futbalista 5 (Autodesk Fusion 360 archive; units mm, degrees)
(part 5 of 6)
sketch "Sketch57" plane through (-1.3145, -0.9192, 0) normal (-0.8195, -0.5731, 0) x axis (0.5731, -0.8195, 0)
  line L1 (38.1702, 34.75) -> (84.1847, 34.75)
  line L2 (38.1702, -17.25) -> (38.1702, 34.75)
  line L3 (81.7843, -17.25) -> (38.1702, -17.25)
  line L4 (81.7843, -19.95) -> (81.7843, -17.25)
  line L5 (84.1847, -19.95) -> (81.7843, -19.95)
  line L6 (84.1847, 34.75) -> (84.1847, -19.95)
  line L7 (48.1702, -17.25) -> (38.1702, -17.25)
  line L8 (48.1702, -12.25) -> (48.1702, -17.25)
  line L9 (74.2849, -22.25) -> (74.2849, -17.25)
  line L10 (80.2624, -22.25) -> (74.2849, -22.25)
  line L11 (80.2624, -17.25) -> (80.2624, -22.25)
  line L12 (74.2849, -17.25) -> (80.2624, -17.25)
  line L13 (45.6702, -20) -> (45.6702, -12.25)
  line L14 (50.6702, -20) -> (50.6702, -12.25)
  circle C1 centre (48.1702, -12.25) radius 2.5
  arc A1 centre (77.2736, -17.25) radius 2.9887 clockwise from (74.2849, -17.25) to (80.2624, -17.25)
  point P4 (38.1702, -17.25)
  point P8 (38.1702, -17.25)
  point P10 (48.1702, -12.25)
  point P11 (48.1702, -12.25)
  point P15 (80.2624, -17.25)
  point P17 (80.2624, -17.25)
  point P12 (74.2849, -17.25)
  point P16 (74.2849, -17.25)
  point P19 (45.6702, -12.25)
  point P21 (50.6702, -12.25)
  point P9 (48.1702, -17.25)
  coincident P4 P8
  perpendicular L2 L7
  perpendicular L7 L8
  coincident P10 P11
  tangent L11 A1
  coincident P15 P17
  coincident P12 P16
  coincident C1 P19
  tangent C1 L13
  perpendicular L3 L13
  coincident C1 P21
  tangent C1 L14
  dimension "d457" distance P8 P9 = 10
  dimension "d458" distance P9 P10 = 5
extrude "Extrude91" cut sketch "Sketch57" profile of L3 L7 L8 C1 L12 A1 L13 L14 against normal blind 2
mirror "Mirror1" mirrorStitchTolerance 0.1
sketch "Sketch58" plane through (59.4825, 10.4884, 0) normal (-0.9848, -0.1736, 0) x axis (0.1736, -0.9848, 0)
  line L1 (-54.7182, 34.75) -> (-57.5849, 34.75)
  line L2 (-54.7182, 32.75) -> (-54.7182, 34.75)
  line L3 (-40.9979, 32.75) -> (-54.7182, 32.75)
  line L4 (-40.9979, 39.3) -> (-40.9979, 32.75)
  line L5 (-57.5849, 39.3) -> (-40.9979, 39.3)
  line L6 (-57.5849, 34.75) -> (-57.5849, 39.3)
  line L7 (-54.7182, 39.3) -> (-54.7182, 34.75)
  point P3 (-54.7182, 34.75)
  point P8 (-54.7182, 34.75)
  point P9 (-54.7182, 39.3)
  coincident P3 P8
  coincident L5 P9
  perpendicular L5 L7
extrude "Extrude93" cut sketch "Sketch58" profile of L2 L3 L4 L5 L7 against normal blind 1.5
extrude "Extrude94" cut of existing geometry blind -3
offset_faces "OffsetFaces27" distance -1
sketch "Sketch59" plane through (0, 0, -17.25) normal (0, 0, 1) x axis (-1, 0, 0)
  line L1 (83.7288, 11.3904) -> (80.9129, 9.7647)
  line L2 (32, -74.955) -> (32, -78.2065)
  line L3 (53.851, -57.8417) -> (53.851, -46.8417)
  line L4 (48.851, -57.8417) -> (53.851, -57.8417)
  line L5 (48.851, -46.8417) -> (48.851, -57.8417)
  line L6 (53.851, -46.8417) -> (48.851, -46.8417)
  line L7 (53.851, -6.8417) -> (48.851, -6.8417)
  line L8 (53.851, -17.8417) -> (53.851, -6.8417)
  line L9 (48.851, -17.8417) -> (53.851, -17.8417)
  line L10 (48.851, -6.8417) -> (48.851, -17.8417)
  line L11 (-19.5656, 26.7114) -> (0, 15.4153)
  line L12 (-28.5443, 4.7598) -> (-18.3943, 22.3402)
  line L13 (-57.5696, 17.8226) -> (-32.9156, 3.5886)
  line L14 (-56.1424, 9.7285) -> (-57.5696, 17.8226)
  line L15 (-60.8695, 8.895) -> (-56.1424, 9.7285)
  line L16 (-62.6555, 19.0241) -> (-60.8695, 8.895)
  line L17 (-59.3277, 19.6109) -> (-62.6555, 19.0241)
  line L18 (-59.5626, 19.2042) -> (-59.3277, 19.6109)
  line L19 (-58.9695, 18.8618) -> (-59.5626, 19.2042)
  line L20 (-45.7195, 41.8114) -> (-58.9695, 18.8618)
  line L21 (-23, 28.6943) -> (-45.7195, 41.8114)
  line L22 (-23, 32.2) -> (-23, 28.6943)
  line L23 (-11.5, 32.2) -> (-23, 32.2)
  line L24 (-11.5, 59.2) -> (-11.5, 32.2)
  line L25 (-5.5, 59.2) -> (-11.5, 59.2)
  line L26 (-5.5, 58.2) -> (-5.5, 59.2)
  line L27 (5.5, 58.2) -> (-5.5, 58.2)
  line L28 (5.5, 59.2) -> (5.5, 58.2)
  line L29 (11.5, 59.2) -> (5.5, 59.2)
  line L30 (11.5, 32.2) -> (11.5, 59.2)
  line L31 (23, 32.2) -> (11.5, 32.2)
  line L32 (23, 28.6943) -> (23, 32.2)
  line L33 (45.7195, 41.8114) -> (23, 28.6943)
  line L34 (59.0695, 18.6886) -> (45.7195, 41.8114)
  line L35 (32.9156, 3.5886) -> (59.0695, 18.6886)
  line L36 (18.3943, 22.3402) -> (28.5443, 4.7598)
  line L37 (0, 15.4153) -> (19.5656, 26.7114)
  line L38 (23, -2.1362) -> (13.35, -7.7076)
  line L39 (23, -21.1848) -> (23, -2.1362)
  line L40 (13.35, -21.1848) -> (23, -21.1848)
  line L41 (13.35, -7.7076) -> (13.35, -21.1848)
  line L42 (-13.35, -21.1848) -> (-13.35, -7.7076)
  line L43 (-23, -21.1848) -> (-13.35, -21.1848)
  line L44 (-23, -2.1362) -> (-23, -21.1848)
  line L45 (-13.35, -7.7076) -> (-23, -2.1362)
  line L46 (-80.9129, 9.7647) -> (-83.7288, 11.3904)
  line L47 (-32, -78.2065) -> (-32, -74.955)
  line L48 (-22.0255, 78.4674) -> (-22.0255, 81.579)
  line L49 (-51.7288, 66.816) -> (-48.9129, 65.1903)
  line L50 (34.3708, 72.532) -> (31.3708, 67.3359)
  line L51 (45.6292, 66.032) -> (34.3708, 72.532)
  line L52 (42.6292, 60.8359) -> (45.6292, 66.032)
  line L53 (31.3708, 67.3359) -> (42.6292, 60.8359)
  line L54 (48.9129, 65.1903) -> (51.7288, 66.816)
  line L55 (22.0255, 81.579) -> (22.0255, 78.4674)
  line L56 (-74, 6.5) -> (-80, 6.5)
  line L57 (-74, -6.5) -> (-74, 6.5)
  line L58 (-80, -6.5) -> (-74, -6.5)
  line L59 (-80, 6.5) -> (-80, -6.5)
  line L60 (45.6292, -66.032) -> (42.6292, -60.8359)
  line L61 (34.3708, -72.532) -> (45.6292, -66.032)
  line L62 (31.3708, -67.3359) -> (34.3708, -72.532)
  line L63 (42.6292, -60.8359) -> (31.3708, -67.3359)
  line L64 (74, -6.5) -> (80, -6.5)
  line L65 (74, 6.5) -> (74, -6.5)
  line L66 (80, 6.5) -> (74, 6.5)
  line L67 (80, -6.5) -> (80, 6.5)
  line L68 (-45.6292, -66.032) -> (-34.3708, -72.532)
  line L69 (-42.6292, -60.8359) -> (-45.6292, -66.032)
  line L70 (-31.3708, -67.3359) -> (-42.6292, -60.8359)
  line L71 (-34.3708, -72.532) -> (-31.3708, -67.3359)
  line L72 (-13.35, -60.5) -> (13.35, -60.5)
  line L73 (-13.35, -30.3) -> (-13.35, -60.5)
  line L74 (10.15, -27.1) -> (-10.15, -27.1)
  line L75 (13.35, -60.5) -> (13.35, -30.3)
  line L76 (-34.3708, 72.532) -> (-45.6292, 66.032)
  line L77 (-31.3708, 67.3359) -> (-34.3708, 72.532)
  line L78 (-42.6292, 60.8359) -> (-31.3708, 67.3359)
  line L79 (-45.6292, 66.032) -> (-42.6292, 60.8359)
  line L80 (-52.7675, -48.5711) -> (-54.5535, -38.442)
  line L81 (-54.4417, -48.8663) -> (-52.7675, -48.5711)
  line L82 (-56.2277, -38.7372) -> (-54.4417, -48.8663)
  line L83 (-54.5535, -38.442) -> (-56.2277, -38.7372)
  line L84 (-46.0708, -47.3903) -> (-47.8568, -37.2612)
  line L85 (-50.7979, -48.2238) -> (-46.0708, -47.3903)
  line L86 (-52.5839, -38.0947) -> (-50.7979, -48.2238)
  line L87 (-47.8568, -37.2612) -> (-52.5839, -38.0947)
  line L88 (22.151, -57.8417) -> (22.151, -46.8417)
  line L89 (16.151, -57.8417) -> (22.151, -57.8417)
  line L90 (16.151, -46.8417) -> (16.151, -57.8417)
  line L91 (22.151, -46.8417) -> (16.151, -46.8417)
  line L92 (-64.5876, 18.4639) -> (-41.4358, 58.564)
  line L93 (-62.8391, 8.5477) -> (-64.5876, 18.4639)
  line L94 (-64.5133, 8.2525) -> (-62.8391, 8.5477)
  line L95 (-65.9099, 16.1735) -> (-64.5133, 8.2525)
  line L96 (-71.4358, 6.6024) -> (-65.9099, 16.1735)
  line L97 (-85.2616, 14.5848) -> (-71.4358, 6.6024)
  line L98 (-30, -65.1664) -> (-30, -81.1311)
  line L99 (30, -65.1664) -> (-30, -65.1664)
  line L100 (30, -81.1311) -> (30, -65.1664)
  line L101 (71.4358, 6.6024) -> (85.2616, 14.5848)
  line L102 (41.4358, 58.564) -> (71.4358, 6.6024)
  line L103 (55.2616, 66.5463) -> (41.4358, 58.564)
  line L104 (20.0255, 60.7) -> (20.0255, 82.8712)
  line L105 (-20.0255, 60.7) -> (20.0255, 60.7)
  line L106 (-20.0255, 82.8712) -> (-20.0255, 60.7)
  line L107 (-41.4358, 58.564) -> (-55.2616, 66.5463)
  line L108 (63.1108, 21.0218) -> (59.0695, 18.6886)
  line L109 (49.7608, 44.1446) -> (45.7195, 41.8114)
  line L110 (-63.1108, 21.0218) -> (-59.0695, 18.6886)
  line L111 (-49.7608, 44.1446) -> (-45.7195, 41.8114)
  line L112 (-13.35, -65.1664) -> (-13.35, -60.5)
  line L113 (13.35, -65.1664) -> (13.35, -60.5)
  line L114 (-58.9695, 18.8618) -> (-59.0695, 18.6886)
  arc A1 centre (0, 0) radius 81.5 clockwise from (80.9129, 9.7647) to (32, -74.955)
  arc A2 centre (0, 0) radius 84.5 clockwise from (83.7288, 11.3904) to (32, -78.2065)
  circle C1 centre (-41.0955, 46.0692) radius 1.7
  circle C2 centre (41.0955, 46.0692) radius 1.7
  circle C3 centre (-57.0248, -52.0589) radius 1.7
  arc A3 centre (-21.1656, 23.9402) radius 3.2 clockwise from (-19.5656, 26.7114) to (-18.3943, 22.3402)
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  point P46 (59.0695, 18.6886)
  point P145 (59.0695, 18.6886)
  point P146 (63.1108, 21.0218)
  point P45 (45.7195, 41.8114)
  point P147 (45.7195, 41.8114)
  point P148 (49.7608, 44.1446)
  point P150 (-63.1108, 21.0218)
  point P32 (-45.7195, 41.8114)
  point P151 (-45.7195, 41.8114)
  point P152 (-49.7608, 44.1446)
  point P94 (-13.35, -60.5)
  point P153 (-13.35, -60.5)
  point P154 (-13.35, -65.1664)
  point P93 (13.35, -60.5)
  point P155 (13.35, -60.5)
  point P156 (13.35, -65.1664)
  point P31 (-58.9695, 18.8618)
  point P157 (-58.9695, 18.8618)
  coincident P46 P145
  coincident L102 P146
  perpendicular L102 L108
  coincident P45 P147
  coincident L102 P148
  perpendicular L102 L109
  coincident L92 P150
  perpendicular L92 L110
  coincident P32 P151
  coincident L92 P152
  perpendicular L92 L111
  coincident P94 P153
  coincident L99 P154
  perpendicular L99 L112
  coincident P93 P155
  coincident L99 P156
  perpendicular L99 L113
  coincident P31 P157
  perpendicular L19 L114
extrude "Extrude95" cut sketch "Sketch59" profile of L17 L18 L19 L20 L34 L72 L92 L99 L102 L108 L109 L110 L111 L112 L113 L114 against normal blind 5 and along normal blind 1
extrude "Extrude96" add of existing geometry blind 40
sketch "Sketch60" plane through (0, 61.1848, 0) normal (0, 1, 0) x axis (-1, 0, 0)
  line L1 (-13.35, 0) -> (-13.35, -17.25)
  line L2 (13.35, -17.25) -> (13.35, 0)
  line L3 (23, -17.25) -> (13.35, -17.25)
  line L4 (23, 28.6416) -> (23, -17.25)
  line L5 (-9, 14.6416) -> (9, 14.6416)
  line L6 (-23, -17.25) -> (-23, 28.6416)
  line L7 (-13.35, -17.25) -> (-23, -17.25)
  line L8 (23, 28.6416) -> (-23, 28.6416)
  arc A1 centre (0, 0) radius 13.35 clockwise from (-13.35, 0) to (13.35, 0)
  arc A2 centre (9, 28.6416) radius 14 clockwise from (23, 28.6416) to (9, 14.6416)
  arc A3 centre (-9, 28.6416) radius 14 clockwise from (-9, 14.6416) to (-23, 28.6416)
  point P12 (-23, 28.6416)
  point P15 (-23, 28.6416)
  point P8 (23, 28.6416)
  point P16 (23, 28.6416)
  coincident P12 P15
  coincident P8 P16
fillet "Fillet7" radius 1
extrude "Extrude97" add sketch "Sketch60" along normal blind 3.9816
extrude "Extrude98" cut of existing geometry blind 28.5
sketch "Sketch61" plane through (-23, 0, 0) normal (-1, 0, 0) x axis (0, -1, 0)
  line L1 (-61.1848, 21.1583) -> (13.8152, 21.1583)
  line L2 (-61.1848, 28.6416) -> (-61.1848, 21.1583)
  line L3 (-65.1664, 28.6416) -> (-61.1848, 28.6416)
  line L4 (-65.1664, -17.25) -> (-65.1664, 28.6416)
  line L5 (-2.1362, -17.25) -> (-65.1664, -17.25)
  line L6 (-2.1362, 0) -> (-2.1362, -17.25)
  line L7 (28.6943, -17.25) -> (28.6943, 0)
  line L8 (32.2, -17.25) -> (28.6943, -17.25)
  line L9 (32.2, 4.6416) -> (32.2, -17.25)
  line L10 (22.2, 14.6416) -> (32.2, 4.6416)
  line L11 (13.8152, 14.6416) -> (22.2, 14.6416)
  line L12 (13.8152, 21.1583) -> (13.8152, 14.6416)
  closed curve K1 centre (13.2791, 0)
  circle C1 centre (-12.3417, -11.9) radius 1.7
  circle C2 centre (-52.3417, -11.9) radius 1.7
extrude "Extrude99" cut sketch "Sketch61" profile of C2 against normal blind 9.65
extrude "Extrude100" new body of existing geometry blind 7 second side blind -3
extrude "Extrude101" cut of existing geometry blind -3.2
fillet "Fillet8" radius 3.2
offset_faces "OffsetFaces28" distance 0.4
sketch "Sketch62" plane through (0, 0, -17.25) normal (0, 0, -1) x axis (1, 0, 0)
  line L1 (10.15, -57.3) -> (-10.15, -57.3)
  line L2 (13.35, -30.3) -> (13.35, -54.1)
  line L3 (-10.15, -27.1) -> (10.15, -27.1)
  line L4 (-13.35, -54.1) -> (-13.35, -30.3)
  line L5 (-9.3809, -52) -> (-6.5191, -52)
  line L6 (-6.2839, -51.8642) -> (-4.853, -49.3858)
  line L7 (-4.853, -49.1142) -> (-6.2839, -46.6358)
  line L8 (-6.5191, -46.5) -> (-9.3809, -46.5)
  line L9 (-9.6161, -46.6358) -> (-11.047, -49.1142)
  line L10 (-11.047, -49.3858) -> (-9.6161, -51.8642)
  line L11 (9.6161, -51.8642) -> (11.047, -49.3858)
  line L12 (11.047, -49.1142) -> (9.6161, -46.6358)
  line L13 (4.853, -49.3858) -> (6.2839, -51.8642)
  line L14 (6.2839, -46.6358) -> (4.853, -49.1142)
  line L15 (9.3809, -46.5) -> (6.5191, -46.5)
  line L16 (6.5191, -52) -> (9.3809, -52)
  line L17 (-6.2839, -38.0642) -> (-4.853, -35.5858)
  line L18 (-4.853, -35.3142) -> (-6.2839, -32.8358)
  line L19 (-11.047, -35.5858) -> (-9.6161, -38.0642)
  line L20 (-9.6161, -32.8358) -> (-11.047, -35.3142)
  line L21 (-6.5191, -32.7) -> (-9.3809, -32.7)
  line L22 (-9.3809, -38.2) -> (-6.5191, -38.2)
  line L23 (9.6161, -38.0642) -> (11.047, -35.5858)
  line L24 (11.047, -35.3142) -> (9.6161, -32.8358)
  line L25 (4.853, -35.5858) -> (6.2839, -38.0642)
  line L26 (6.2839, -32.8358) -> (4.853, -35.3142)
  line L27 (9.3809, -32.7) -> (6.5191, -32.7)
  line L28 (6.5191, -38.2) -> (9.3809, -38.2)
  arc A1 centre (-10.15, -54.1) radius 3.2 clockwise from (-10.15, -57.3) to (-13.35, -54.1)
  arc A2 centre (10.15, -54.1) radius 3.2 clockwise from (13.35, -54.1) to (10.15, -57.3)
  arc A3 centre (10.15, -30.3) radius 3.2 clockwise from (10.15, -27.1) to (13.35, -30.3)
  arc A4 centre (-10.15, -30.3) radius 3.2 clockwise from (-13.35, -30.3) to (-10.15, -27.1)
  circle C1 centre (-7.95, -49.25) radius 1.5
  circle C2 centre (7.95, -49.25) radius 1.5
  circle C3 centre (-7.95, -35.45) radius 1.5
  circle C4 centre (7.95, -35.45) radius 1.5
  circle C5 centre (-7.95, -49.25) radius 3.1
  circle C6 centre (7.95, -49.25) radius 1.5
  circle C7 centre (7.95, -49.25) radius 3.1
  circle C8 centre (-7.95, -35.45) radius 1.5
  circle C9 centre (-7.95, -35.45) radius 3.1
  circle C10 centre (7.95, -35.45) radius 1.5
  circle C11 centre (7.95, -35.45) radius 3.1
  point P19 (-6.5191, -52)
  point P20 (-9.3809, -52)
  concentric C1 C5
  coincident C5 P19
  coincident C5 P20
  dimension "d496" diameter C5 = 6.2
  dimension "d499" C-Pattern1-Angle = 360
  dimension "d502" R-Pattern1-uDistance = 15.9
  dimension "d503" R-Pattern1-vDistance = 13.8
extrude "Extrude102" new body sketch "Sketch62" profile of A1 L1 A2 L2 A3 L3 A4 L4 C5 L5 L6 L7 L8 L9 L10 L11 L12 L13 L14 L15 C7 L16 L17 L18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 against normal blind 4
offset_faces "OffsetFaces29" distance -0.2
offset_faces "OffsetFaces30" distance 0.2
extrude "Extrude105" new body sketch "Sketch62" profile of C1 C5 L5 L6 L7 L8 L9 L10 against normal blind 3
move "Move5"
move "Move6"
copy_paste_bodies "CopyPasteBodies1"
move "Move7"
move "Move8"
combine "Combine6"
sketch "Sketch63" plane through (23, 0, 0) normal (1, 0, 0) x axis (0, 1, 0)
  line L1 (-13.8152, 21.1583) -> (61.1848, 21.1583)
  line L2 (-13.8152, 14.6416) -> (-13.8152, 21.1583)
  line L3 (-22.2, 14.6416) -> (-13.8152, 14.6416)
  line L4 (-32.2, 4.6416) -> (-22.2, 14.6416)
  line L5 (-32.2, -17.25) -> (-32.2, 4.6416)
  line L6 (-28.6943, -17.25) -> (-32.2, -17.25)
  line L7 (-28.6943, 0) -> (-28.6943, -17.25)
  line L8 (2.1362, -17.25) -> (2.1362, 0)
  line L9 (65.1664, -17.25) -> (2.1362, -17.25)
  line L10 (65.1664, 28.6416) -> (65.1664, -17.25)
  line L11 (61.1848, 28.6416) -> (65.1664, 28.6416)
  line L12 (61.1848, 21.1583) -> (61.1848, 28.6416)
  line L13 (7.7076, 0) -> (7.7076, -17.25)
  line L14 (-15.4153, 0) -> (-15.4153, -2.75)
  line L15 (-15.4153, -12.75) -> (-15.4153, -17.25)
  line L16 (61.1848, 14.6416) -> (-13.8152, 14.6416)
  line L17 (-13.8152, 14.6416) -> (61.1848, 14.6416)
  line L18 (33.6848, 10.6416) -> (33.6848, 12.6416)
  line L19 (13.6848, 10.6416) -> (33.6848, 10.6416)
  line L20 (13.6848, 12.6416) -> (13.6848, 10.6416)
  line L21 (33.6848, 12.6416) -> (13.6848, 12.6416)
  line L22 (17.7076, -17.25) -> (7.7076, -17.25)
  line L23 (17.7076, -17.25) -> (17.7076, 8.6416)
  line L24 (17.7076, 8.6416) -> (55.1664, 8.6416)
  line L25 (55.1664, -17.25) -> (55.1664, 8.6416)
  line L26 (17.7076, -17.25) -> (21.7076, -13.25)
  line L27 (51.1666, -13.25) -> (21.7076, -13.25)
  line L28 (55.1664, -17.25) -> (51.1666, -13.25)
  line L29 (51.1664, -17.25) -> (47.1666, -13.25)
  line L30 (21.7076, -17.25) -> (25.7076, -13.25)
  line L31 (-32.2, -2.75) -> (-29.7, -17.25)
  closed curve K1 centre (-13.2791, 0)
  closed curve K2 centre (0, 0)
  closed curve K3 centre (0, 0)
  closed curve K4 centre (-15.4153, -7.75)
  point P16 (7.7076, -17.25)
  point P33 (7.7076, -17.25)
  point P37 (55.1664, -17.25)
  point P44 (-29.7, -17.25)
  point P45 (-32.2, -2.75)
  point P29 (33.6848, 12.6416)
  point P30 (33.6848, 10.6416)
  point P31 (13.6848, 10.6416)
  point P34 (17.7076, -17.25)
  point P38 (21.7076, -13.25)
  point P39 (51.1666, -13.25)
  perpendicular L17 L18
  coincident P16 P33
  perpendicular L13 L22
  perpendicular L22 L23
  coincident L9 P37
  perpendicular L9 L25
  perpendicular L25 L27
  coincident L6 P44
  coincident L5 P45
  dimension "d509" distance P29 P30 = 2
  dimension "d510" distance P30 P31 = 20
  dimension "d511" distance P33 P34 = 10
  dimension "d563" distance P38 P39 = 29.459 (= "33.459 mm - 4 mm")
extrude "Extrude103" cut sketch "Sketch63" profile of L9 L23 L24 L25 against normal blind 23
extrude "Extrude104" cut sketch "Sketch63" profile of L18 L19 L20 L21 against normal blind 46
offset_faces "OffsetFaces31" distance -0.6
extrude "Extrude106" add of existing geometry blind -8.851 (= "-30.851 mm + 22 mm") second side blind 12.851
extrude "Extrude107" cut of existing geometry blind -8.851
sketch "Sketch64" plane through (-23, 0, 0) normal (-1, 0, 0) x axis (0, -1, 0)
  line L1 (-33.6848, 10.6416) -> (-13.6848, 10.6416)
  line L2 (-33.6848, 12.6416) -> (-33.6848, 10.6416)
  line L3 (-13.6848, 12.6416) -> (-33.6848, 12.6416)
  line L4 (-13.6848, 10.6416) -> (-13.6848, 12.6416)
  line L5 (-61.1848, 21.1583) -> (13.8152, 21.1583)
  line L6 (-61.1848, 28.6416) -> (-61.1848, 21.1583)
  line L7 (-65.1664, 28.6416) -> (-61.1848, 28.6416)
  line L8 (-65.1664, -17.25) -> (-65.1664, 28.6416)
  line L9 (-2.829, -17.25) -> (-65.1664, -17.25)
  line L10 (-2.829, 0) -> (-2.829, -17.25)
  line L11 (29.3871, -17.25) -> (29.3871, 0)
  line L12 (32.2, -17.25) -> (29.3871, -17.25)
  line L13 (32.2, 4.6416) -> (32.2, -17.25)
  line L14 (22.2, 14.6416) -> (32.2, 4.6416)
  line L15 (13.8152, 14.6416) -> (22.2, 14.6416)
  line L16 (13.8152, 21.1583) -> (13.8152, 14.6416)
  circle C1 centre (-52.3417, -11.9) radius 1.7
  closed curve K1 centre (13.2791, 0)
  circle C2 centre (-12.3417, -11.9) radius 1.7
  circle C3 centre (-52.3417, -11.9) radius 3
  circle C4 centre (-12.3417, -11.9) radius 3
  concentric C1 C3
  concentric C2 C4
  dimension "d528" diameter C3 = 6
  dimension "d529" diameter C4 = 6
extrude "Extrude108" new body sketch "Sketch64" profile of C1 C2 C3 C4 along normal blind 15 and along normal blind 4
copy_paste_bodies "CopyPasteBodies2"
move "Move9"
extrude "Extrude109" add of existing geometry blind 7 second side blind -3
sketch "Sketch65" plane through (-9.9995, 56.71, 0) normal (0.1736, -0.9848, 0) x axis (0.9848, 0.1736, 0)
  line L1 (58.0967, 22.35) -> (58.9501, 22.35)
  line L2 (58.0967, 19.45) -> (58.0967, 22.35)
  line L3 (58.7501, 19.45) -> (58.0967, 19.45)
  line L4 (58.7501, 4.55) -> (58.7501, 19.45)
  line L5 (58.0967, 4.55) -> (58.7501, 4.55)
  line L6 (58.0967, 1.4) -> (58.0967, 4.55)
  line L7 (58.7501, 1.4) -> (58.0967, 1.4)
  line L8 (58.7501, -14.9) -> (58.7501, 1.4)
  line L9 (58.0967, -14.9) -> (58.7501, -14.9)
  line L10 (58.0967, -19.95) -> (58.0967, -14.9)
  line L11 (60.4001, -19.95) -> (58.0967, -19.95)
  line L12 (60.4001, 34.75) -> (60.4001, -19.95)
  line L13 (58.9501, 34.75) -> (60.4001, 34.75)
  line L14 (58.9501, 22.35) -> (58.9501, 34.75)
  line L15 (58.0967, 19.45) -> (43.2001, 19.45)
  line L16 (43.2001, 19.45) -> (43.2001, 5.8429)
  line L17 (43.2001, 5.8429) -> (44.493, 4.55)
  line L18 (44.493, 4.55) -> (58.0967, 4.55)
  line L19 (43.2001, 22.35) -> (58.0967, 22.35)
  line L20 (58.0967, 1.4) -> (44.9001, 1.4)
  line L21 (44.9001, 1.4) -> (44.9001, -14.9)
  line L22 (44.9001, -14.9) -> (58.0967, -14.9)
  line L23 (43.2001, 34.75) -> (43.2001, 22.35)
  line L24 (43.2167, -16.95) -> (43.2167, 0)
  curve K1 (43.2167, 0) -> (-16.8565, 0)
  line L25 (58.0967, -16.95) -> (43.2167, -16.95)
  line L26 (34.178, 22.35) -> (43.2001, 22.35)
  point P29 (43.2167, -16.95)
  point P31 (43.2167, -16.95)
  point P32 (58.0967, -16.95)
  point P22 (43.2001, 22.35)
  point P33 (43.2001, 22.35)
  point P34 (34.178, 22.35)
  coincident P29 P31
  coincident L10 P32
  perpendicular L10 L25
  coincident P22 P33
  coincident K1 P34
  perpendicular L23 L26
extrude "Extrude110" add sketch "Sketch65" profile of L2 L6 L10 L15 L16 L17 L18 L19 L20 L21 L22 L24 K1 L25 L26 against normal blind 29
sketch "Sketch66" plane through (0, 0, 22.35) normal (0, 0, 1) x axis (-1, 0, 0)
  line L1 (-30.4818, -75.9085) -> (-29.9937, -78.6767)
  line L2 (-20.754, -81.6022) -> (-20.754, -79.1234)
  line L3 (-42.1787, -95.3578) -> (-46.6309, -70.1085)
  line L4 (-18.6235, -91.2044) -> (-42.1787, -95.3578)
  line L5 (-23.6593, -62.645) -> (-18.6235, -91.2044)
  line L6 (-48.055, -66.9466) -> (-23.6593, -62.645)
  line L7 (-47.6146, -69.4441) -> (-48.055, -66.9466)
  line L8 (-25.681, -65.5766) -> (-47.6146, -69.4441)
  line L9 (-25.681, -65.5766) -> (-22.9598, -81.0092)
  line L10 (-32.1039, -66.7092) -> (-30.4818, -75.9085)
  line L11 (-30.0823, -63.7775) -> (-27.2822, -79.6575)
  arc A1 centre (0, 0) radius 81.8 clockwise from (-20.754, -79.1234) to (-30.4818, -75.9085)
  arc A2 centre (0, 0) radius 84.2 clockwise from (-20.754, -81.6022) to (-29.9937, -78.6767)
  arc A3 centre (0, 0) radius 84.2 clockwise from (-46.6309, -70.1085) to (-47.6146, -69.4441)
  circle C1 centre (0, 0) radius 84.2
  circle C2 centre (0, 0) radius 81.8
  point P1 (0, 0)
  point P13 (0, 0)
  point P7 (-46.6309, -70.1085)
  point P12 (-47.6146, -69.4441)
  point P14 (-47.6146, -69.4441)
  point P16 (-22.9598, -81.0092)
  point P18 (-32.1039, -66.7092)
  point P19 (-30.0823, -63.7775)
  point P20 (-27.2822, -79.6575)
  point P17 (-30.4818, -75.9085)
  point P15 (-25.681, -65.5766)
  coincident P1 P13
  coincident P7 C1
  coincident P12 P14
  perpendicular L5 L8
  coincident C1 P16
  coincident L8 P18
  perpendicular L8 L10
  coincident L6 P19
  coincident C1 P20
  concentric C1 C2
  coincident P17 C2
  dimension "d540" distance P14 P15 = 22.272
extrude "Extrude111" cut sketch "Sketch66" profile of L1 A1 A2 L3 L4 L5 L6 A3 C1 L8 L9 L10 L11 C2 along normal blind 12.4 and against normal blind 37.25
sketch "Sketch67" plane through (0, 0, 41.4) normal (0, 0, 1) x axis (-1, 0, 0)
  line L1 (14, 32.2) -> (20.5595, 32.2)
  line L2 (14, 17.8152) -> (14, 32.2)
  line L3 (-14, 17.8152) -> (14, 17.8152)
  line L4 (-14, 32.2) -> (-14, 17.8152)
  line L5 (-20.5595, 32.2) -> (-14, 32.2)
  line L6 (-48.2472, 71.7946) -> (-20.5595, 32.2)
  line L7 (20.5595, 32.2) -> (48.2472, 71.7946)
  line L8 (-59.5395, 10.912) -> (-60.091, 10.8147)
  line L9 (-56.7009, 3.4516) -> (-57.8018, 9.6952)
  line L10 (-58.4691, 1.6166) -> (-57.9176, 1.7139)
  line L11 (-61.3077, 9.0771) -> (-60.2068, 2.8334)
  line L12 (-58.5616, -6.4972) -> (-57.813, -10.7427)
  line L13 (-57.8862, -5.2447) -> (-58.4438, -5.9974)
  line L14 (-56.1766, -4.7622) -> (-57.4768, -4.9914)
  line L15 (-54.4512, -10.8044) -> (-55.4236, -5.2894)
  line L16 (-56.2786, -11.7866) -> (-54.9784, -11.5574)
  line L17 (-57.5313, -11.172) -> (-56.75, -11.6887)
  line L18 (-56.2173, -19.7921) -> (-55.4687, -24.0376)
  line L19 (-55.542, -18.5396) -> (-56.0995, -19.2923)
  line L20 (-53.8324, -18.0571) -> (-55.1325, -18.2863)
  line L21 (-52.1069, -24.0993) -> (-53.0794, -18.5843)
  line L22 (-53.9343, -25.0815) -> (-52.6342, -24.8523)
  line L23 (-55.1871, -24.4669) -> (-54.4057, -24.9836)
  line L24 (-23, 13.8152) -> (-23, -61.1848)
  line L25 (23, 13.8152) -> (-23, 13.8152)
  line L26 (23, -61.1848) -> (23, 13.8152)
  line L27 (-23, -61.1848) -> (23, -61.1848)
  line L28 (-47.0259, -36.2146) -> (-47.4127, -34.0213)
  line L29 (-69, 10) -> (-69, -10)
  line L30 (-67, -10) -> (-67, 10)
  line L31 (-71, -10) -> (-69, -10)
  line L32 (-71, 10) -> (-71, -10)
  line L33 (-69, 10) -> (-71, 10)
  line L34 (-65, 10) -> (-67, 10)
  line L35 (-65, -10) -> (-65, 10)
  line L36 (-67, -10) -> (-65, -10)
  line L37 (0, -22.5) -> (0, -1.75)
  line L38 (71, 10) -> (71, -10)
  line L39 (69, 10) -> (69, -10)
  line L40 (71, -10) -> (69, -10)
  line L41 (67, -10) -> (65, -10)
  line L42 (65, -10) -> (65, 10)
  line L43 (67, -10) -> (67, 10)
  line L44 (69, 10) -> (71, 10)
  line L45 (65, 10) -> (67, 10)
  circle C1 centre (41.0955, 46.0692) radius 3
  circle C2 centre (-57.0248, -52.0589) radius 3
  circle C3 centre (-41.0955, 46.0692) radius 3
  circle C4 centre (76.0955, -10.3372) radius 3
  circle C5 centre (47, -60.7321) radius 3
  circle C6 centre (-76.0955, -10.3372) radius 3
  arc A1 centre (0, 0) radius 86.5 clockwise from (48.2472, 71.7946) to (-48.2472, 71.7946)
  arc A2 centre (-59.8305, 9.3375) radius 1.5 clockwise from (-61.3077, 9.0771) to (-60.091, 10.8147)
  arc A3 centre (-59.279, 9.4348) radius 1.5 clockwise from (-59.5395, 10.912) to (-57.8018, 9.6952)
  arc A4 centre (-58.1781, 3.1911) radius 1.5 clockwise from (-56.7009, 3.4516) to (-57.9176, 1.7139)
  arc A5 centre (-58.7296, 3.0938) radius 1.5 clockwise from (-58.4691, 1.6166) to (-60.2068, 2.8334)
  arc A6 centre (-57.1728, -10.6298) radius 0.65 clockwise from (-57.5313, -11.172) to (-57.813, -10.7427)
  arc A7 centre (-57.9214, -6.3843) radius 0.65 clockwise from (-58.5616, -6.4972) to (-58.4438, -5.9974)
  arc A8 centre (-57.3639, -5.6316) radius 0.65 clockwise from (-57.8862, -5.2447) to (-57.4768, -4.9914)
  arc A9 centre (-56.0637, -5.4023) radius 0.65 clockwise from (-56.1766, -4.7622) to (-55.4236, -5.2894)
  arc A10 centre (-55.0913, -10.9172) radius 0.65 clockwise from (-54.4512, -10.8044) to (-54.9784, -11.5574)
  arc A11 centre (-56.3915, -11.1465) radius 0.65 clockwise from (-56.2786, -11.7866) to (-56.75, -11.6887)
  arc A12 centre (-55.5772, -19.6792) radius 0.65 clockwise from (-56.2173, -19.7921) to (-56.0995, -19.2923)
  arc A13 centre (-55.0196, -18.9265) radius 0.65 clockwise from (-55.542, -18.5396) to (-55.1325, -18.2863)
  arc A14 centre (-53.7195, -18.6972) radius 0.65 clockwise from (-53.8324, -18.0571) to (-53.0794, -18.5843)
  arc A15 centre (-52.7471, -24.2121) radius 0.65 clockwise from (-52.1069, -24.0993) to (-52.6342, -24.8523)
  arc A16 centre (-54.0472, -24.4414) radius 0.65 clockwise from (-53.9343, -25.0815) to (-54.4057, -24.9836)
  arc A17 centre (-54.8286, -23.9247) radius 0.65 clockwise from (-55.1871, -24.4669) to (-55.4687, -24.0376)
  arc A18 centre (-50.1737, -35.6389) radius 3.2 clockwise from (-47.0259, -36.2146) to (-47.4127, -34.0213)
  point P72 (-67, -10)
  point P88 (67, -10)
  point P73 (-69, -10)
  point P85 (69, -10)
  point P74 (-69, 10)
  point P86 (69, 10)
  point P75 (-67, 10)
  point P90 (67, 10)
  point P77 (-71, -10)
  point P83 (71, -10)
  point P78 (-71, 10)
  point P84 (71, 10)
  point P79 (-65, 10)
  point P89 (65, 10)
  point P80 (-65, -10)
  point P87 (65, -10)
  parallel L29 L30
  perpendicular L29 L31
  perpendicular L31 L32
  perpendicular L29 L33
  perpendicular L30 L34
  perpendicular L34 L35
  perpendicular L30 L36
  symmetric P72 L37 P88
  symmetric P73 L37 P85
  symmetric P74 L37 P86
  symmetric P75 L37 P90
  symmetric P77 L37 P83
  symmetric P78 L37 P84
  symmetric P79 L37 P89
  symmetric P80 L37 P87
extrude "Extrude112" cut sketch "Sketch67" profile of L29 L30 L31 L32 L33 L34 L35 L36 L38 L39 L40 L41 L42 L43 L44 L45 against normal blind 8.65
extrude "Extrude113" new body sketch "Sketch12" profile of C1 L1 L2 L3 L7 L11 along normal blind 100
offset_faces "OffsetFaces32" distance 0.5
combine "Combine7"
extrude "Extrude114" cut sketch "Sketch66" profile of A2 L3 L4 L5 C1 against normal blind 39.3
combine "Combine8"
sketch "Sketch68" plane through (42.5438, 7.5016, 0) normal (0.9848, 0.1736, 0) x axis (-0.1736, 0.9848, 0)
  line L1 (60.1209, 5.7183) -> (60.3849, 5.7183)
  line L2 (60.1209, 1.0474) -> (60.1209, 5.7183)
  line L3 (60.1209, 1.0474) -> (69.4611, 1.0474)
  line L4 (72.273, 34.75) -> (72.273, 5.5341)
  line L5 (69.4621, 34.75) -> (72.273, 34.75)
  line L6 (69.4621, 22.35) -> (69.4621, 34.75)
  line L7 (60.1209, 22.35) -> (69.4621, 22.35)
  line L8 (60.1209, 19.45) -> (60.1209, 22.35)
  line L9 (57.5849, 19.45) -> (60.1209, 19.45)
  line L10 (57.5849, 18.2817) -> (57.5849, 19.45)
  line L11 (60.3849, 18.2817) -> (57.5849, 18.2817)
  line L12 (60.3849, 17.55) -> (60.3849, 18.2817)
  line L13 (60.8321, 17.55) -> (60.3849, 17.55)
  line L14 (60.8321, 6.45) -> (60.8321, 17.55)
  line L15 (60.3849, 6.45) -> (60.8321, 6.45)
  line L16 (60.3849, 5.7183) -> (60.3849, 6.45)
  line L17 (60.8321, 18.2817) -> (60.3849, 18.2817)
  line L18 (60.8321, 17.55) -> (60.8321, 18.2817)
  line L19 (60.8321, 5.7183) -> (60.3849, 5.7183)
  line L20 (60.8321, 6.45) -> (60.8321, 5.7183)
  line L21 (57.5849, 5.4619) -> (60.1209, 5.4619)
  line L22 (60.8321, 5.4619) -> (60.8321, 5.7183)
  line L23 (60.1209, 5.4619) -> (60.8321, 5.4619)
  line L24 (57.5849, 18.2817) -> (57.5849, 5.4619)
  line L25 (60.6849, 7.3185) -> (60.9849, 7.3185)
  line L26 (60.9849, 17.25) -> (60.9849, 7.3185)
  line L27 (60.6849, 17.25) -> (60.9849, 17.25)
  line L28 (60.6849, 7.3185) -> (60.6849, 17.25)
  line L29 (60.9849, 18.2817) -> (60.8321, 18.2817)
  line L30 (60.9849, 17.25) -> (60.9849, 18.2817)
  line L31 (60.9849, 5.4619) -> (60.8321, 5.4619)
  line L32 (60.9849, 7.3185) -> (60.9849, 5.4619)
  closed curve K1 centre (245, 0)
  point P15 (60.3849, 18.2817)
  point P20 (60.3849, 18.2817)
  point P17 (60.8321, 17.55)
  point P22 (60.8321, 17.55)
  point P2 (60.3849, 5.7183)
  point P23 (60.3849, 5.7183)
  point P18 (60.8321, 6.45)
  point P25 (60.8321, 6.45)
  point P26 (60.1209, 5.4619)
  point P29 (60.1209, 5.4619)
  point P27 (57.5849, 5.4619)
  point P30 (57.5849, 5.4619)
  point P14 (57.5849, 18.2817)
  point P31 (57.5849, 18.2817)
  point P34 (60.9849, 17.25)
  point P37 (60.9849, 17.25)
  point P32 (60.9849, 7.3185)
  point P39 (60.9849, 7.3185)
  coincident P15 P20
  perpendicular L14 L17
  coincident P17 P22
  perpendicular L13 L18
  coincident P2 P23
  perpendicular L16 L19
  coincident P18 P25
  perpendicular L15 L20
  perpendicular L21 L22
  coincident P26 P29
  perpendicular L2 L23
  coincident P27 P30
  coincident P14 P31
  perpendicular L26 L29
  coincident P34 P37
  perpendicular L27 L30
  perpendicular L22 L31
  coincident P32 P39
  perpendicular L31 L32
extrude "Extrude115" cut sketch "Sketch68" profile of L1 L2 L11 L12 L13 L14 L15 L16 L17 L18 L19 L20 L21 L22 L23 L24 L25 L26 L27 L28 L29 L30 L31 L32 along normal blind 2 and against normal blind 0.8
extrude "Extrude116" cut of existing geometry blind 16.35
sketch "Sketch69" plane through (41.756, 7.3627, 0) normal (0.9848, 0.1736, 0) x axis (-0.1736, 0.9848, 0)
  line L1 (60.1209, 7.3185) -> (60.6849, 7.3185)
  line L2 (60.6849, 7.3185) -> (60.9849, 7.3185)
  line L3 (60.9849, 18.2817) -> (60.9849, 7.3185)
  line L4 (60.1209, 18.2817) -> (60.9849, 18.2817)
  line L5 (60.1209, 19.45) -> (60.1209, 18.2817)
  line L6 (57.5849, 19.45) -> (60.1209, 19.45)
  line L7 (57.5849, 7.3185) -> (57.5849, 19.45)
  line L8 (57.5849, 7.3185) -> (60.1209, 7.3185)
  line L9 (60.9849, 19.45) -> (60.9849, 18.2817)
  line L10 (60.1209, 19.45) -> (60.9849, 19.45)
  line L11 (60.1209, 4.55) -> (57.5849, 4.55)
  line L12 (60.1209, 4.55) -> (57.5849, 4.55)
  line L13 (57.5849, 4.55) -> (57.5849, 7.3185)
  line L14 (60.9849, 4.55) -> (60.1209, 4.55)
  line L15 (60.9849, 7.3185) -> (60.9849, 4.55)
  point P5 (60.9849, 18.2817)
  point P10 (60.9849, 18.2817)
  point P7 (60.1209, 19.45)
  point P12 (60.1209, 19.45)
  point P9 (57.5849, 7.3185)
  point P15 (57.5849, 7.3185)
  point P14 (57.5849, 4.55)
  point P16 (57.5849, 4.55)
  point P13 (60.1209, 4.55)
  point P17 (60.1209, 4.55)
  point P4 (60.9849, 7.3185)
  point P19 (60.9849, 7.3185)
  coincident P5 P10
  perpendicular L6 L9
  coincident P7 P12
  perpendicular L5 L10
  coincident P9 P15
  coincident P14 P16
  coincident P13 P17
  perpendicular L3 L14
  coincident P4 P19
  perpendicular L2 L15
extrude "Extrude117" cut sketch "Sketch69" along normal blind 0.8
extrude "Extrude118" cut sketch "Sketch63" profile of L5 L6 L9 L26 L27 L29 L30 against normal blind 46
extrude "Extrude119" cut of existing geometry blind -5
extrude "Extrude120" cut of existing geometry blind -5
extrude "Extrude121" cut of existing geometry blind -5
extrude "Extrude122" cut of existing geometry blind -5
chamfer "Chamfer9" distance 10
sketch "Sketch71" plane through (23, 0, 0) normal (1, 0, 0) x axis (0, 1, 0)
  line L1 (-29.7, -17.25) -> (-32.2, -2.75)
  line L2 (-29.3871, -17.25) -> (-29.7, -17.25)
  line L3 (-29.3871, 0) -> (-29.3871, -17.25)
  line L4 (2.829, -17.25) -> (2.829, 0)
  line L5 (17.7076, -17.25) -> (2.829, -17.25)
  line L6 (17.7076, 8.6416) -> (17.7076, -17.25)
  line L7 (45.1664, 8.6416) -> (17.7076, 8.6416)
  line L8 (55.1664, -1.3584) -> (45.1664, 8.6416)
  line L9 (55.1664, -17.25) -> (55.1664, -1.3584)
  line L10 (65.1664, -17.25) -> (55.1664, -17.25)
  line L11 (65.1664, 28.6416) -> (65.1664, -17.25)
  line L12 (61.1848, 28.6416) -> (65.1664, 28.6416)
  line L13 (61.1848, 21.1583) -> (61.1848, 28.6416)
  line L14 (-13.8152, 21.1583) -> (61.1848, 21.1583)
  line L15 (-13.8152, 14.6416) -> (-13.8152, 21.1583)
  line L16 (-22.2, 14.6416) -> (-13.8152, 14.6416)
  line L17 (-32.2, 4.6416) -> (-22.2, 14.6416)
  line L18 (-32.2, -2.75) -> (-32.2, 4.6416)
  line L19 (38.6848, 12.6416) -> (33.6848, 12.6416)
  line L20 (38.6848, 10.6416) -> (38.6848, 12.6416)
  line L21 (33.6848, 10.6416) -> (38.6848, 10.6416)
  line L22 (8.6848, 10.6416) -> (33.6848, 10.6416)
  line L23 (8.6848, 12.6416) -> (8.6848, 10.6416)
  line L24 (33.6848, 12.6416) -> (8.6848, 12.6416)
  line L25 (61.2228, 5.3131) -> (56.5304, 0.6208)
  line L26 (61.2228, 14.6979) -> (56.5304, 19.3903)
  line L27 (56.5304, 19.3903) -> (51.838, 14.6979)
  line L28 (51.838, 5.3131) -> (56.5304, 0.6208)
  line L29 (58.8766, 17.0441) -> (54.1842, 17.0441)
  line L30 (58.8766, 2.9669) -> (58.8766, 17.0441)
  line L31 (54.1842, 2.9669) -> (58.8766, 2.9669)
  line L32 (54.1842, 17.0441) -> (54.1842, 2.9669)
  line L33 (47.1456, 10.0055) -> (51.838, 14.6979)
  line L34 (51.838, 5.3131) -> (47.1456, 10.0055)
  line L35 (51.838, 5.3131) -> (61.2228, 14.6979)
  line L36 (2.829, -17.25) -> (-29.3871, -17.25)
  line L37 (-22.0468, -17.25) -> (-32.2, -2.75)
  closed curve K1 centre (-13.2791, 0)
  arc A1 centre (56.5304, 10.0055) radius 6.636 clockwise from (61.2228, 14.6979) to (61.2228, 5.3131)
  arc A2 centre (56.5304, 10.0055) radius 6.636 clockwise from (51.838, 5.3131) to (51.838, 14.6979)
  point P38 (58.8766, 2.9669)
  point P36 (54.1842, 17.0441)
  point P4 (-29.3871, -17.25)
  point P41 (-29.3871, -17.25)
  point P8 (2.829, -17.25)
  point P42 (2.829, -17.25)
  point P2 (-32.2, -2.75)
  point P43 (-32.2, -2.75)
  point P44 (-22.0468, -17.25)
  tangent L25 A1
  tangent L26 A1
  tangent A2 L27
  tangent A2 L28
  horizontal L29
  vertical L30
  horizontal L31
  vertical L32
  midpoint L25 P38
  midpoint L27 P36
  tangent A2 L33
  perpendicular L28 L33
  tangent A2 L34
  perpendicular L28 L35
  coincident P4 P41
  coincident P8 P42
  coincident P2 P43
  coincident L36 P44
extrude "Extrude123" cut sketch "Sketch71" profile of L1 L2 L3 L25 L26 A1 A2 L27 L28 L29 L30 L31 L32 L33 L34 L35 L36 L37 against normal blind 46
work_plane "WorkPlane3" RotateAngle 0
sketch "Sketch72" plane through (-2.0687, 0, 2.7395) normal (-0.6026, 0, 0.798) x axis (-0.798, 0, -0.6026)
  line L1 (-27.2528, -51.7816) -> (-16.0056, -51.7816)
  line L2 (-27.2528, -61.1848) -> (-27.2528, -51.7816)
  line L3 (-17.3572, -61.1848) -> (-27.2528, -61.1848)
  line L4 (-27.2119, -61.2228) -> (-30.0397, -56.5304)
  line L5 (-30.0397, -56.5304) -> (-24.3841, -47.1456)
  closed curve K1 centre (-24.4425, -65.7816)
  closed curve K2 centre (-24.4425, -47.2791)
  closed curve K3 centre (-24.3841, -56.5304)
  point P2 (-16.0056, -51.7816)
  point P7 (-16.0056, -51.7816)
  point P5 (-17.3572, -61.1848)
  point P10 (-17.3572, -61.1848)
  coincident P2 P7
  tangent K1 L1
  horizontal L1
  perpendicular L1 L2
  coincident P5 P10
  perpendicular L2 L3
extrude "Extrude124" cut sketch "Sketch72" profile of K1 K2 L1 L2 L3 L4 L5 distance 6
mirror "Mirror2" mirrorStitchTolerance 0.1
offset_faces "OffsetFaces33" distance -5
sketch "Sketch1" plane through (0, 0, 0) normal (0, 0, 1) x axis (1, 0, 0)
  line L1 (20.3961, 22) -> (-20.3961, 22)
  line L2 (0, 14) -> (0, 30)
  line L3 (15, 18.0192) -> (15, 25.9808)
  line L4 (-15, 18.0192) -> (-15, 25.9808)
  line L5 (-8.1051, -22) -> (-15, -25.9808)
  line L6 (-29.2506, 6.6635) -> (-8.8545, -28.6635)
  line L7 (-12.1244, -7) -> (-25.9808, -15)
  line L8 (-23.1051, 3.9808) -> (-30, 0)
  line L9 (23.1051, 3.9808) -> (30, 0)
  line L10 (8.8545, -28.6635) -> (29.2506, 6.6635)
  line L11 (12.1244, -7) -> (25.9808, -15)
  line L12 (8.1051, -22) -> (15, -25.9808)
  circle C1 centre (0, 0) radius 30
  arc A1 centre (0, 44) radius 30 clockwise from (20.3961, 22) to (-20.3961, 22)
  arc A2 centre (-38.1051, -22) radius 30 clockwise from (-29.2506, 6.6635) to (-8.8545, -28.6635)
  arc A3 centre (38.1051, -22) radius 30 clockwise from (8.8545, -28.6635) to (29.2506, 6.6635)
  point P1 (0, 0)
  point P2 (0, 0)
  point P6 (0, 30)
  point P7 (0, 14)
  point P8 (15, 25.9808)
  point P9 (15, 18.0192)
  coincident P1 P2
  horizontal L1
  coincident C1 P6
  midpoint A1 P7
  vertical L2
  coincident C1 P8
  coincident A1 P9
  perpendicular L1 L3
  dimension "d8_1" C-Pattern1-Angle = 360
extrude "Extrude1" new body sketch "Sketch1" distance 3 bodies "koliesko1"
revolve "Revolve1" sketch "Sketch1" AlongAngle 360 named "d11_1"
circular_pattern "C-Pattern1" TotalAngle 360 named "d13_1"
sketch "Sketch2" plane through (-7.5, 12.9904, 0) normal (0.5, -0.866, 0) x axis (0.866, 0.5, 0)
  line L1 (-25.9808, -3) -> (-25.9808, 3)
  line L2 (-19.3834, -3) -> (-25.9808, -3)
  line L3 (-25.9808, 3) -> (-19.3834, 3)
  arc A1 centre (-22, 0) radius 3.9808 clockwise from (-19.3834, 3) to (-19.3834, -3)
  circle C1 centre (-22, 0) radius 1.5
  circle C2 centre (-22, 0) radius 3.9808
  concentric A1 C1
  concentric C1 C2
revolve "Revolve2" sketch "Sketch1" AlongAngle 360 named "d20_1" bodies "valcek"
extrude "Extrude2" cut sketch "Sketch2" profile of C1 against normal blind 2.5 named "d14_1" and along normal blind 32.5 named "d16_1"
offset_faces "OffsetFaces6" distance -0.2
circular_pattern "C-Pattern2" TotalAngle 360 named "d19_1"
offset_faces "OffsetFaces1" distance -0.2 named "d21_1"
circular_pattern "C-Pattern3" TotalAngle 360
sketch "Sketch3" plane through (0, 0, 3) normal (0, 0, 1) x axis (-1, 0, 0)
  line L1 (14.7991, 26.0957) -> (9.0374, 22.7692)
  line L2 (-9.0374, 22.7692) -> (-14.7991, 26.0957)
  curve K1 (-24.2374, -3.558) -> (-9.0374, 22.7692)
  line L3 (-29.9991, -0.2315) -> (-24.2374, -3.558)
  line L4 (-15.2, -19.2113) -> (-15.2, -25.8643)
  curve K2 (15.2, -19.2113) -> (-15.2, -19.2113)
  line L5 (15.2, -25.8643) -> (15.2, -19.2113)
  line L6 (24.2374, -3.558) -> (29.9991, -0.2315)
  curve K3 (9.0374, 22.7692) -> (24.2374, -3.558)
  curve K4 (-15.2, 19.2113) -> (15.2, 19.2113)
  line L7 (-15.2, 25.8643) -> (-15.2, 19.2113)
  line L8 (-24.2374, 3.558) -> (-29.9991, 0.2315)
  curve K5 (-9.0374, -22.7692) -> (-24.2374, 3.558)
  line L9 (-14.7991, -26.0957) -> (-9.0374, -22.7692)
  line L10 (9.0374, -22.7692) -> (14.7991, -26.0957)
  curve K6 (24.2374, 3.558) -> (9.0374, -22.7692)
  line L11 (29.9991, 0.2315) -> (24.2374, 3.558)
  line L12 (15.2, 19.2113) -> (15.2, 25.8643)
  arc A1 centre (0, 0) radius 30 clockwise from (-14.7991, 26.0957) to (14.7991, 26.0957)
  arc A2 centre (0, 0) radius 30 clockwise from (-15.2, -25.8643) to (-29.9991, -0.2315)
  arc A3 centre (0, 0) radius 30 clockwise from (29.9991, -0.2315) to (15.2, -25.8643)
  circle C1 centre (0, 0) radius 14.3685
  circle C2 centre (5.5, -5.5) radius 1.5
  circle C3 centre (-5.5, -5.5) radius 1.5
  circle C4 centre (5.5, 5.5) radius 1.5
  circle C5 centre (-5.5, 5.5) radius 1.5
  arc A4 centre (0, 0) radius 30 clockwise from (-29.9991, 0.2315) to (-15.2, 25.8643)
  arc A5 centre (0, 0) radius 30 clockwise from (14.7991, -26.0957) to (-14.7991, -26.0957)
  arc A6 centre (0, 0) radius 30 clockwise from (15.2, 25.8643) to (29.9991, 0.2315)
  dimension "d26_1" R-Pattern1-uDistance = -11
  dimension "d27_1" R-Pattern1-vDistance = 11
extrude "Extrude3" new body sketch "Sketch3" profile of C1 C2 C3 C4 C5 along normal blind 6 named "d29_1" bodies "spacer"
extrude "Extrude7" cut sketch "Sketch3" profile of C2 C3 C4 C5 along normal blind 6 and against normal blind 6 named "d48_1"
offset_faces "OffsetFaces5" distance -0.2
offset_faces "OffsetFaces7" distance -0.35
split "Split2" bodies "koliesko2 (ten isty tvar)"
copy_paste_bodies "CopyPasteBodies3"
move "Move3"
sketch "Sketch4" plane through (0, 0, 0) normal (0, 0, 1) x axis (1, 0, 0)
  line L1 (30, 0) -> (0, 0)
  line L2 (-7.7646, 28.9778) -> (7.7646, 28.9778)
  line L3 (0, 30) -> (0, 0)
  line L4 (15, 25.9808) -> (0, 0)
  line L5 (-15, 25.9808) -> (0, 0)
  line L6 (-30, 0) -> (0, 0)
  line L7 (-15, -25.9808) -> (0, 0)
  line L8 (15, -25.9808) -> (0, 0)
  line L9 (9.7646, 28.3664) -> (-9.7646, 28.3664)
  line L10 (-19.6837, 22.6396) -> (-29.4483, 5.7268)
  line L11 (-29.4483, -5.7268) -> (-19.6837, -22.6396)
  line L12 (-9.7646, -28.3664) -> (9.7646, -28.3664)
  line L13 (19.6837, -22.6396) -> (29.4483, -5.7268)
  line L14 (29.4483, 5.7268) -> (19.6837, 22.6396)
  line L15 (-9.7646, 28.3664) -> (-9.7646, 22.3664)
  line L16 (9.7646, 28.3664) -> (9.7646, 22.3664)
  line L17 (9.7646, 25.3664) -> (-9.7646, 25.3664)
  line L18 (9.7646, 25.8664) -> (9.7646, 25.3664)
  line L19 (-9.7646, 26.1164) -> (9.7646, 26.1164)
  circle C1 centre (0, 0) radius 30
  arc A1 centre (0, 50.7328) radius 30 clockwise from (9.7646, 22.3664) to (-9.7646, 22.3664)
  circle C2 centre (5.75, -5.75) radius 1.5
  circle C3 centre (-5.75, -5.75) radius 1.5
  circle C4 centre (5.75, 5.75) radius 1.5
  circle C5 centre (-5.75, 5.75) radius 1.5
  circle C6 centre (0, 0) radius 11
  circle C7 centre (0, 0) radius 5
  circle C8 centre (0, 0) radius 20.7328
  point P1 (0, 0)
  point P2 (0, 0)
  point P3 (0, 0)
  point P4 (30, 0)
  point P7 (0, 0)
  point P8 (0, 30)
  point P19 (-9.7646, 28.3664)
  point P20 (9.7646, 28.3664)
  point P34 (-9.7646, 25.3664)
  point P35 (9.7646, 25.3664)
  point P17 (0, 0)
  point P41 (0, 0)
  point P13 (0, 0)
  point P43 (0, 0)
  coincident P1 P2
  coincident P2 P3
  coincident C1 P4
  horizontal L1
  coincident P1 P7
  coincident C1 P8
  perpendicular L2 L3
  coincident C1 P19
  coincident C1 P20
  perpendicular L9 L15
  perpendicular L9 L16
  midpoint L15 P34
  midpoint L16 P35
  perpendicular L9 L18
  coincident P17 P41
  concentric C1 C7
  coincident P13 P43
  tangent A1 C8
  dimension "d58_1" C-Pattern1-Angle = 360
  dimension "d61" C-Pattern2-Angle = 360
  dimension "d84_1" R-Pattern1-uDistance = -11.5
  dimension "d85_1" R-Pattern1-vDistance = 11.5
revolve "Revolve3" sketch "Sketch4" AlongAngle 360 named "d64_1" bodies "valcek (1)"
extrude "Extrude8" new body sketch "Sketch4" profile of C1 L3 L4 L5 A1 L15 L16 L17 L18 distance 3 named "d65_1"
combine "Combine1"
sketch "Sketch6" plane through (0, 0, 0) normal (1, 0, 0) x axis (0, 1, 0)
  line L1 (25.3664, -3) -> (25.3664, 0)
  line L2 (25.3664, 3) -> (25.3664, 0)
  line L3 (0, -3) -> (25.3664, -3)
  line L4 (0, 3) -> (0, -3)
  line L5 (25.3664, 3) -> (0, 3)
  line L6 (25.3664, 0) -> (25.8967, 0.5303)
  line L7 (25.3664, 1.0607) -> (25.8967, 0.5303)
  line L8 (24.8361, 0.5303) -> (25.3664, 1.0607)
  line L9 (30, 3) -> (0, 3)
  line L10 (30, -3) -> (30, 3)
  line L11 (25.3664, -3) -> (30, -3)
  circle C1 centre (25.3664, 0) radius 3
  circle C2 centre (25.3664, 0) radius 0.75
  point P2 (25.3664, 0)
  point P3 (25.3664, 0)
  point P4 (25.3664, -3)
  point P5 (25.3664, 3)
  point P9 (25.8967, 0.5303)
  point P8 (25.3664, 0)
  point P10 (25.3664, 0)
  point P11 (25.3664, 1.0607)
  point P12 (24.8361, 0.5303)
  coincident P2 P3
  coincident C1 P4
  vertical L1
  coincident C1 P5
  parallel L1 L2
  perpendicular L1 L3
  perpendicular L3 L4
  perpendicular L2 L5
  coincident C2 P9
  coincident P8 P10
  coincident L2 P11
  tangent C2 L7
  coincident C2 P12
  tangent C2 L8
  perpendicular L4 L9
  perpendicular L3 L10
  perpendicular L1 L11
offset_faces "OffsetFaces8" distance -0.5 named "d72_1"
revolve "Revolve6" AlongAngle 300 named "d78_1"
extrude "Extrude9" cut sketch "Sketch6" profile of L1 L2 C2 L6 L7 L8 along normal blind 19 and against normal blind 11.265
revolve "Revolve5" sketch "Sketch6" AlongAngle 35 AgainstAngle 35
combine "Combine2"
offset_faces "OffsetFaces9" distance -1 named "d81_1"
offset_faces "OffsetFaces12" distance -0.3
circular_pattern "C-Pattern5" TotalAngle 360 named "d80_1"
combine "Combine3"
offset_faces "OffsetFaces11" distance -0.2 named "d97_1"
extrude "Extrude10" cut sketch "Sketch4" profile of C2 C3 C4 C5 distance 3 named "d86_1"
copy_paste_bodies "CopyPasteBodies5"
move "Move5"
extrude "Extrude11" cut sketch "Sketch4" profile of L1 L3 L4 L5 L6 L7 L8 C7 against normal blind 3 named "d88_1"
extrude "Extrude12" cut sketch "Sketch4" profile of L1 L3 L4 L5 L6 L7 L8 C2 C3 C4 C5 C6 C7 along normal blind 3
extrude "Extrude13" new body sketch "Sketch4" profile of L1 L3 L4 L5 L6 L7 L8 C2 C3 C4 C5 C6 C7 C8 along normal blind 5 and along normal blind 3 named "d94_1" bodies "spacer (1)"
offset_faces "OffsetFaces10" distance -0.2 named "d96_1"
base_feature "Base Feature1"
copy_paste_bodies "CopyPasteBodies3"
component_from_bodies "Body->Comp1"
component_from_bodies "Body->Comp2"
component_from_bodies "Body->Comp3"
component_from_bodies "Body->Comp4"
component_from_bodies "Body->Comp5"
component_from_bodies "Body->Comp6"
component_from_bodies "Body->Comp7"
component_from_bodies "Body->Comp1"
component_from_bodies "Body->Comp2"
component_from_bodies "Body->Comp3"
component_from_bodies "Body->Comp1"
component_from_bodies "Body->Comp8"
component_from_bodies "Body->Comp9"
component_from_bodies "Body->Comp10"
component_from_bodies "Body->Comp11"
component_from_bodies "Body->Comp12"
component_from_bodies "Body->Comp13"
component_from_bodies "Body->Comp14"
component_from_bodies "Body->Comp15"
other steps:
base_feature "Base Feature1"
base_feature "Base Feature1"
base_feature "Base Feature1"
base_feature "Base Feature1" bodies "valcek (1)"
base_feature "Base Feature1" bodies "body"
base_feature "Base Feature1"
base_feature "Base Feature1" bodies "spacer (1)"
base_feature "Base Feature1" bodies "motor bracket (1)"
base_feature "Base Feature1" bodies "motor adapter (1)"
base_feature "Base Feature1"
base_feature "Base Feature1"
base_feature "Base Feature1"
base_feature "Base Feature1"
base_feature "Base Feature1"
base_feature "Base Feature1"
base_feature "Base Feature1" bodies "body hole"
base_feature "Base Feature1"
base_feature "Base Feature1"
base_feature "Base Feature1"
base_feature "Base Feature3"
base_feature "Base Feature5" bodies "body"
base_feature "Base Feature1"
base_feature "Base Feature2"
base_feature "Base Feature3" bodies "motor adapter", "motor bracket", "motor adapter (1)", "motor bracket (1)"
create_component "CreateComponent1"
create_component "CreateComponent2"
create_component "CreateComponent1"
remove_body "RemoveBody1"
create_component "CreateComponent2"
remove_body "RemoveBody2"
create_component "CreateComponent3"
remove_body "RemoveBody3"
create_component "CreateComponent4"
remove_body "RemoveBody4"
create_component "CreateComponent5"
remove_body "RemoveBody5"
create_component "CreateComponent6"
remove_body "RemoveBody6"
create_component "CreateComponent7"
remove_body "RemoveBody7"
create_component "CreateComponent3"
remove_body "RemoveBody1"
create_component "CreateComponent4"
remove_body "RemoveBody2"
create_component "CreateComponent5"
remove_body "RemoveBody3"
create_component "CreateComponent1"
remove_body "RemoveBody1"
create_component "CreateComponent8"
remove_body "RemoveBody8"
create_component "CreateComponent9"
remove_body "RemoveBody9"
create_component "CreateComponent10"
remove_body "RemoveBody10"
create_component "CreateComponent11"
remove_body "RemoveBody11"
create_component "CreateComponent12"
remove_body "RemoveBody12"
create_component "CreateComponent13"
remove_body "RemoveBody13"
create_component "CreateComponent14"
remove_body "RemoveBody14"
create_component "CreateComponent15"
remove_body "RemoveBody15"
named bodies: "motor adapter", "motor bracket", "floor1", "kicker", "shell1", "top", "motor adapter (1)", "motor bracket (1)", "koliesko1", "valcek", "spacer", "koliesko2 (ten isty tvar)", "valcek (1)", "body hole", "body", "spacer (1)"

design "BTS7960 43A HIGH POWER H BRIDGE MODULE"
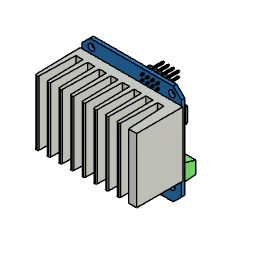
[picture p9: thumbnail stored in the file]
description: STEP AP214
part number: BTS7960 43A HIGH POWER H BRIDGE MODULE
description: Part Number
part number: PCB, BTS7960 43A HIGH POWER H BRIDGE MODULE
part number: HEATSINK, BTS7960 43A HIGH POWER H BRIDGE MODULE
part number: BTN7960 IC, BTS7960 43A HIGH POWER H BRIDGE MODULE
part number: NXP 74HC244D, BUFFER AND LINE DRIVER, BTS7960 43A HIGH POWER H BRIDGE MODULE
